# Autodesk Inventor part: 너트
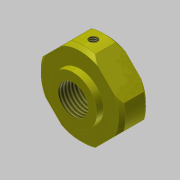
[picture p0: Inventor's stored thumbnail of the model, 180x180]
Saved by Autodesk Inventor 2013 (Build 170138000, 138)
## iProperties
Created: 2020-03
Part Number: 너트
Material: 스테인리스강
Document SubType Name: Modeling
Designer: mduedu
Density: 1 g/cm^3
Author: mduedu
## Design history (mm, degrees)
sketch "스케치1"
  geometry: C1 r 12.5 at (0, 0); 1 further point
  constraints: 1 centre point, 1 coincident
  dimensions: "d0" = 25 diameter of C1
extrude "돌출1" new body sketch "스케치1" distance "d1" = 8; taper "d2" = 0 deg
chamfer "모따기1" distance "d3" = 1; stored, may be unused: second distance "d4" = 2, angle "d5" = 45 deg
sketch "스케치2"
  geometry: L1 (-15.556, 0)-(0, 15.556); L2 (0, 15.556)-(15.556, 0); L3 (15.556, 0)-(0, -15.556); L4 (0, -15.556)-(-15.556, 0); L5 (-15.556, 0)-(15.556, 0); L6 (0, 15.556)-(0, -15.556); C1 r 12.5 at (0, 0) reference; 1 further point
  constraints: 12 end point, 2 midpoint, 2 parallel, 1 horizontal, 1 perpendicular, 1 vertical
  dimensions: "d8" = 22 distance of L1.end L2.end
extrude "돌출2" sketch "스케치2" stored distance "d10" = 8; taper "d11" = 0 deg
sketch "스케치3"
  geometry: C1 r 7 at (0, 0); 1 further point
  constraints: 1 centre point, 1 coincident
  dimensions: "d12" = 14 diameter of C1
extrude "돌출3" join sketch "스케치3" distance "d13" = 2; taper "d14" = 0 deg
hole "구멍1" diameter "d17" = 8.917; stored, may be unused: countersink angle "d21" = 90 deg, drill point angle "d23" = 118 deg; dims "d15" = 10, "d16" = 10, "d18" = 6, "d19" = 4, "d20" = 2, "d22" = 8
sketch "스케치4"
  geometry: 2 further points
  constraints: 1 vertical alignment
  dimensions: "d24" = 4 distance of point (0, 4) point (0, 0)
hole "구멍2" sketch "스케치4" at (0, 4) diameter "d25" = 2.459; stored, may be unused: countersink angle "d29" = 90 deg, drill point angle "d31" = 118 deg; dims "d26" = 6, "d27" = 4, "d28" = 2, "d30" = 8
node "솔리드1"
